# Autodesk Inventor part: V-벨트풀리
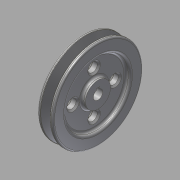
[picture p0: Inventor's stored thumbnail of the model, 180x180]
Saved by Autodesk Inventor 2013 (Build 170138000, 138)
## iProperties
Created: 2015-09
Part Number: V-벨트풀리
Material: 강철, 연강
Document SubType Name: Modeling
Designer: mduedu
Density: 1 g/cm^3
Author: mduedu
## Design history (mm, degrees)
sketch "스케치1"
  geometry: L1 (-10, 0)-(10, 0); L2 (-10, 0)-(-10, 57.5); L3 (-10, 57.5)-(-6.062, 57.5); L4 (-6.062, 57.5)-(-2.001, 45); L5 (-2.001, 45)-(2.001, 45); L6 (2.001, 45)-(6.062, 57.5); L7 (6.062, 57.5)-(10, 57.5); L8 (10, 57.5)-(10, 0); L9 (0, 0)-(0, 45); L10 (-10, 53)-(10, 53); 3 further points
  constraints: 20 end point, 6 point on line, 3 perpendicular, 2 midpoint, 2 parallel, 2 symmetric about line, 1 coincident, 1 collinear, 1 equal length, 1 horizontal, 1 vertical, 1 vertical alignment
  dimensions: "d0" = 20 distance between parallel lines of L8 L2; "d2" = 115 diameter of L3 L1; "d5" = 8 distance between parallel lines of L5 L10; "d6" = 9.2 distance of point (4.6, 53) point (-4.6, 53); "d7" = 36 deg angle of L6 L4; "d40" = 4.5 distance between parallel lines of L10 L3
revolve "회전1" sketch "스케치1" stored, may be unused: angle "d8" = 90 deg
sketch "스케치2"
  geometry: C1 r 16 at (0, 0); C2 r 41 at (0, 0); 1 further point
  constraints: 2 centre point, 2 coincident
  dimensions: "d9" = 32 diameter of C1; "d41" = 82 diameter of C2
extrude "돌출5" cut sketch "스케치2" distance "d42" = 5; taper "d43" = 0 deg
hole "구멍2" diameter "d46" = 12; stored, may be unused: countersink angle "d50" = 90 deg, drill point angle "d52" = 118 deg; dims "d44" = 10, "d45" = 10, "d47" = 6, "d48" = 4, "d49" = 2, "d51" = 8
sketch "스케치8"
  geometry: L1 (-2, 5.657)-(2, 5.657); L2 (2, 5.657)-(2, 7.8); L3 (2, 7.8)-(-2, 7.8); L4 (-2, 7.8)-(-2, 5.657); A1 r 6 centre (0, 0) between (-2, 5.657) and (2, 5.657) reference; 1 further point
  constraints: 8 end point, 2 parallel, 2 point on circle, 1 horizontal, 1 perpendicular
  dimensions: "d53" = 4 distance of L2.end L3.end; "d55" = 13.8 dimension on A1 L3
extrude "돌출6" cut sketch "스케치8" stored distance "d56" = 5; taper "d57" = 0 deg
sketch "스케치9"
  geometry: C1 r 6 at (0, 27); 1 further point
  constraints: 1 centre point, 1 vertical alignment
  dimensions: "d61" = 12 diameter of C1; "d62" = 27 distance of C1.centre point (0, 0)
extrude "돌출7" cut sketch "스케치9" stored distance "d63" = 5; taper "d64" = 0 deg
chamfer "모따기3" distance "d65" = 2; stored, may be unused: second distance "d66" = 2, angle "d67" = 45 deg
fillet "모깎기5" dims "d71" = 2, "d72" = 1, "d73" = 0.5
fillet "모깎기6" dims "d74" = 3
fillet "모깎기7" dims "d75" = 3
fillet "모깎기8" dims "d76" = 3
sketch "스케치10"
  geometry: C1 r 47.5 at (0, 0); 1 further point
  constraints: 1 centre point, 1 coincident, 1 other
  dimensions: "d77" = 95 diameter of C1
extrude "돌출8" join sketch "스케치10" distance "d80" = 0.5; taper "d81" = 0 deg
node "솔리드1"
mirror "대칭2"
pattern_circular "원형 패턴1" dims "d69" = 360 deg
